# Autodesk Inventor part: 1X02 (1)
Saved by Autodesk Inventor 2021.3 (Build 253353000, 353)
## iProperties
Created: 2021-12
Part Number: 1X02 (1)
Material: Generic
Document SubType Name: Modeling
Designer: Administrator
Density: 1 g/cm^3
Appearance: Default
Title: 1X02 (1)
Author: Administrator
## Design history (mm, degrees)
feature "Body1"
body "Solid1"
